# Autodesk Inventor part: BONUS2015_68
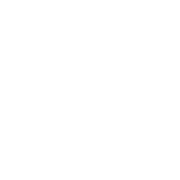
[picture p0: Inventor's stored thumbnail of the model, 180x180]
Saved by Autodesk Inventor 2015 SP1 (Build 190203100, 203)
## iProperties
Created: 2015-05
Part Number: BONUS2015_68
Material: Generisch
Document SubType Name: Modeling
Density: 1 g/cm^3
Appearance: Vorgabe
xx: 68
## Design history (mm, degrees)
